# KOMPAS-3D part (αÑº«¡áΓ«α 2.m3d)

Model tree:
1. Эскиз:1
2. Операция выдавливания:1
     Толщина стенки 1 = 2; Толщина стенки 2 = 8; Расстояние 1 = 1
3. Эскиз:3
4. Операция выдавливания:2
     Толщина стенки 1 = 2; Толщина стенки 2 = 6; Расстояние 1 = 5.5
5. Эскиз:4
6. Операция выдавливания:3
     Толщина стенки 1 = 2; Толщина стенки 2 = 6; Расстояние 1 = 1
7. Эскиз:5
8. Эскиз:6
9. Операция выдавливания:4
     Толщина стенки 1 = 2; Толщина стенки 2 = 2.5; Расстояние 1 = 50
10. Эскиз:7
11. Вырезать элемент выдавливания:1
     Толщина стенки 2 = 1.5; Расстояние 1 = 40
12. Эскиз:8
13. Операция выдавливания:5
     Толщина стенки 1 = 2; Толщина стенки 2 = 2.5; Расстояние 1 = 50
14. Эскиз:9
15. Вырезать элемент выдавливания:2
     Толщина стенки 2 = 1.5; Расстояние 1 = 40
16. Эскиз:10
17. Операция выдавливания:6
     Толщина стенки 1 = 2; Толщина стенки 2 = 2.5; Расстояние 1 = 10
18. Эскиз:11
19. Операция выдавливания:7
     Толщина стенки 1 = 2; Толщина стенки 2 = 6; Расстояние 1 = 1
20. Эскиз:12
21. Операция выдавливания:8
     Толщина стенки 1 = 2; Толщина стенки 2 = 6; Расстояние 1 = 5.5
22. Эскиз:13
23. Операция выдавливания:9
     Толщина стенки 1 = 2; Толщина стенки 2 = 8; Расстояние 1 = 1
24. Эскиз:14
25. Вырезать элемент выдавливания:3
     Толщина стенки 2 = 1.5; Расстояние 1 = 23
26. Эскиз:15
27. Вырезать элемент выдавливания:4
     Толщина стенки 2 = 1.5; Расстояние 1 = 1
28. Эскиз:16
29. Вырезать элемент выдавливания:5
     Расстояние 1 = 150
30. Эскиз:18
31. Операция выдавливания:11
     Толщина стенки 1 = 8; Толщина стенки 2 = 8; Расстояние 1 = 10; Расстояние 2 = 0.4
